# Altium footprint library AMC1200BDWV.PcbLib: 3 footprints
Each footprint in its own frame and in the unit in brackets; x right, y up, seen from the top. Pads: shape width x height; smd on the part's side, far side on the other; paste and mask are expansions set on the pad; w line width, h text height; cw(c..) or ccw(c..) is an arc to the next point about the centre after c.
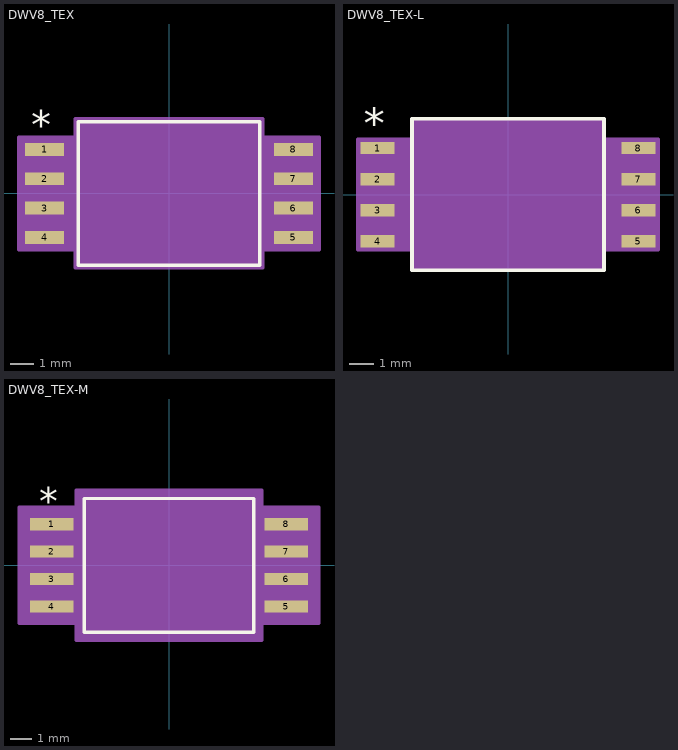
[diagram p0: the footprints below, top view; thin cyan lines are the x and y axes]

## DWV8_TEX [mil]
pads (8):
  rect 67x22 smd paste+0 mask+0: 1(-212,75) 2(-212,25) 3(-212,-25) 4(-212,-75) 5(212,-75) 6(212,-25) 7(212,25) 8(212,75)
Top Overlay:
  lines w6: -154.5,-122 -154.5,122 154.5,122 154.5,-122 -154.5,-122
  text "*" at -234.5,92 h50
Mechanical 13:
  lines w0: -12,117 ccw(c0,117) 12,117
  lines w1: -231.5,-85 -149.5,-85 -149.5,-65 -231.5,-65 -231.5,-85 ; -231.5,-35 -149.5,-35 -149.5,-15 -231.5,-15 -231.5,-35 ; -231.5,15 -149.5,15 -149.5,35 -231.5,35 -231.5,15 ; -231.5,65 -149.5,65 -149.5,85 -231.5,85 -231.5,65 ; -149.5,-117 -149.5,117 149.5,117 149.5,-117 -149.5,-117 ; 149.5,-85 231.5,-85 231.5,-65 149.5,-65 149.5,-85 ; 149.5,-35 231.5,-35 231.5,-15 149.5,-15 149.5,-35 ; 149.5,15 231.5,15 231.5,35 149.5,35 149.5,15 ; 149.5,65 231.5,65 231.5,85 149.5,85 149.5,65
  text "*" at -147,64 h50
Mechanical 15:
  region: -159.5,-96 -255.5,-96 -255.5,96 -159.5,96 -159.5,127 159.5,127 159.5,96 255.5,96 255.5,-96 159.5,-96 159.5,-127 -159.5,-127
  lines w6: -255.5,-96 -159.5,-96 -159.5,-127 159.5,-127 159.5,-96 255.5,-96 255.5,96 159.5,96 159.5,127 -159.5,127 -159.5,96 -255.5,96 -255.5,-96
3D body "DWV8_TEX.step": height 110.12, standoff 0, extent -231.5,-117.01 231.5,117.01
3D body "DWV8_TEX.step": height 110.12, standoff 0, extent -231.5,-117.01 231.5,117.01

## DWV8_TEX-L [mil]
pads (8):
  rect 55x20 smd paste+0 mask+0: 1(-210,75) 2(-210,25) 3(-210,-25) 4(-210,-75) 5(210,-75) 6(210,-25) 7(210,25) 8(210,75)
Top Overlay:
  lines w6: -154.5,-122 154.5,-122 154.5,122 -154.5,122 -154.5,-122
  text "*" at -232.5,90 h50
Mechanical 13:
  lines w0: -12,117 ccw(c0,117) 12,117
  lines w1: -231.5,-85 -231.5,-65 -149.5,-65 -149.5,-85 -231.5,-85 ; -231.5,-35 -231.5,-15 -149.5,-15 -149.5,-35 -231.5,-35 ; -231.5,15 -231.5,35 -149.5,35 -149.5,15 -231.5,15 ; -231.5,65 -231.5,85 -149.5,85 -149.5,65 -231.5,65 ; -149.5,-117 149.5,-117 149.5,117 -149.5,117 -149.5,-117 ; 149.5,-85 149.5,-65 231.5,-65 231.5,-85 149.5,-85 ; 149.5,-35 149.5,-15 231.5,-15 231.5,-35 149.5,-35 ; 149.5,15 149.5,35 231.5,35 231.5,15 149.5,15 ; 149.5,65 149.5,85 231.5,85 231.5,65 149.5,65
  text "*" at -147,64 h50
Mechanical 15:
  region: -153.5,-89 -241.5,-89 -241.5,89 -153.5,89 -153.5,121 153.5,121 153.5,89 241.5,89 241.5,-89 153.5,-89 153.5,-121 -153.5,-121
  lines w6: -241.5,-89 -241.5,89 -153.5,89 -153.5,121 153.5,121 153.5,89 241.5,89 241.5,-89 153.5,-89 153.5,-121 -153.5,-121 -153.5,-89 -241.5,-89
3D body "DWV8_TEX.step": height 110.12, standoff 0, extent -231.5,-117.01 231.5,117.01

## DWV8_TEX-M [mil]
pads (8):
  rect 79x22 smd paste+0 mask+0: 1(-214,75) 2(-214,25) 3(-214,-25) 4(-214,-75) 5(214,-75) 6(214,-25) 7(214,25) 8(214,75)
Top Overlay:
  lines w6: -154.5,-122 -154.5,122 154.5,122 154.5,-122 -154.5,-122
  text "*" at -236.5,92 h50
Mechanical 13:
  lines w0: -12,117 ccw(c0,117) 12,117
  lines w1: -231.5,-85 -149.5,-85 -149.5,-65 -231.5,-65 -231.5,-85 ; -231.5,-35 -149.5,-35 -149.5,-15 -231.5,-15 -231.5,-35 ; -231.5,15 -149.5,15 -149.5,35 -231.5,35 -231.5,15 ; -231.5,65 -149.5,65 -149.5,85 -231.5,85 -231.5,65 ; -149.5,-117 -149.5,117 149.5,117 149.5,-117 -149.5,-117 ; 149.5,-85 231.5,-85 231.5,-65 149.5,-65 149.5,-85 ; 149.5,-35 231.5,-35 231.5,-15 149.5,-15 149.5,-35 ; 149.5,15 231.5,15 231.5,35 149.5,35 149.5,15 ; 149.5,65 231.5,65 231.5,85 149.5,85 149.5,65
  text "*" at -147,64 h50
Mechanical 15:
  region: -169.5,-106 -273.5,-106 -273.5,106 -169.5,106 -169.5,137 169.5,137 169.5,106 273.5,106 273.5,-106 169.5,-106 169.5,-137 -169.5,-137
  lines w6: -273.5,-106 -169.5,-106 -169.5,-137 169.5,-137 169.5,-106 273.5,-106 273.5,106 169.5,106 169.5,137 -169.5,137 -169.5,106 -273.5,106 -273.5,-106
3D body "DWV8_TEX.step": height 110.12, standoff 0, extent -231.5,-117.01 231.5,117.01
